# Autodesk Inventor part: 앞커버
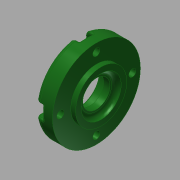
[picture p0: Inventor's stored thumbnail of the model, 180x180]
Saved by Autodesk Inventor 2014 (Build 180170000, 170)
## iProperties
Created: 2015-11
Part Number: 앞커버
Material: 알루미늄 6061
Document SubType Name: Modeling
Designer: mduedu
Density: 1 g/cm^3
Appearance: 매끄러움 - 짙은 산림 녹색
Author: mduedu
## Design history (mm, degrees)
sketch "스케치1"
  geometry: L1 (-7, 0)-(7, 0); L2 (-7, 0)-(-7, 27.5); L3 (-7, 27.5)-(4, 27.5); L4 (4, 27.5)-(4, 16); L5 (4, 16)-(7, 16); L6 (7, 16)-(7, 0); 2 further points
  constraints: 12 end point, 3 perpendicular, 2 parallel, 1 coincident, 1 horizontal, 1 midpoint
  dimensions: "d0" = 14 distance of L1.start L1.end; "d1" = 55 diameter of L3 L1; "d2" = 3 distance of L4.end L5.end; "d3" = 32 diameter of L5 L1
revolve "회전1" sketch "스케치1" stored, may be unused: angle "d4" = 90 deg
hole "구멍1" diameter "d7" = 25; stored, may be unused: countersink angle "d11" = 90 deg, drill point angle "d13" = 0 deg; dims "d5" = 10, "d6" = 10, "d8" = 6, "d9" = 4, "d10" = 2, "d12" = 3
hole "구멍2" diameter "d16" = 25; stored, may be unused: countersink angle "d20" = 90 deg, drill point angle "d22" = 0 deg; dims "d17" = 6, "d18" = 4, "d19" = 2, "d21" = 7, "d63" = 10, "d64" = 10
hole "구멍3" diameter "d25" = 17; stored, may be unused: countersink angle "d29" = 90 deg, drill point angle "d31" = 0 deg; dims "d23" = 10, "d24" = 10, "d26" = 6, "d27" = 4, "d28" = 2, "d30" = 4.2
chamfer "모따기1" distance "d32" = 0.6; stored, may be unused: second distance "d33" = 2, angle "d34" = 30 deg
fillet "모깎기1" dims "d35" = 0.3
fillet "모깎기2" dims "d36" = 3
fillet "모깎기3" dims "d37" = 3
sketch "스케치2" dims "d39" = 45
  geometry: C1 r 12.846 at (0, 0) reference; C2 r 24.5 at (0, 0) reference; 6 further points
  constraints: 2 vertical alignment, 1 coincident, 7 other
  dimensions: "d42" = 360 deg dimension on point (0, 0) point (0, 22.5) (derived)
sketch "스케치3"
  geometry: 8 further points
  constraints: 4 coincident
hole "구멍4" sketch "스케치3" at (-22.5, 0), (0, -22.5), (22.5, 0), (0, 22.5) diameter "d44" = 4.5; stored, may be unused: countersink angle "d48" = 90 deg, drill point angle "d50" = 0 deg; dims "d45" = 6, "d46" = 8, "d47" = 4.6, "d49" = 8
sketch "스케치4"
  geometry: L1 (-4, 0)-(-4, -4.708); L2 (4, 0)-(4, -4.708); A1 r 4 centre (0, 0) between (-4, 0) and (4, 0) reference; A2 r 27.5 centre (0, 22.5) between (-4, -4.708) and (4, -4.708) reference; 3 further points
  constraints: 4 end point, 4 point on circle, 2 tangent, 1 parallel, 1 vertical
extrude "돌출1" cut sketch "스케치4" stored distance "d51" = 0; taper "d52" = 0 deg
fillet "모깎기5" dims "d56" = 0.3
fillet "모깎기6" dims "d57" = 1
node "솔리드1"
pattern_circular "원형 패턴1" dims angle "d54" = 360 deg
